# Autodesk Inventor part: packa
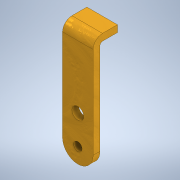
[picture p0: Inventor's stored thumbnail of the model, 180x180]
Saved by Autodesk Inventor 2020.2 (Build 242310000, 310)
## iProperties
Created: 2020-04
Part Number: packa
Material: Brass, Soft Yellow, Welded
Document SubType Name: Modeling
Designer: freem
Density: 8.5 g/cm^3
Appearance: Weld - Brass
Author: freem
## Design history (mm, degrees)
sketch "Sketch1"
  geometry: L1 (0, 4)-(63, 4); L2 (68.5, -1.5)-(68.5, -10.3); L3 (63, -1.5)-(96.882, 32.382); L4 (64.5, -10.3)-(64.5, -1.5); L5 (63, 0)-(0, 0); L6 (68.5, -10.3)-(64.5, -10.3); L7 (0, 0)-(0, 4); A1 r 5.5 centre (63, -1.5) between (68.5, -1.5) and (63, 4); A2 r 1.5 centre (63, -1.5) between (64.5, -1.5) and (63, 0); 1 further point
  constraints: 14 end point, 4 point on circle, 2 centre point, 2 horizontal, 2 tangent, 1 coincident, 1 perpendicular, 1 symmetric about line, 1 vertical, 2 other
  dimensions: "d2" = 5.5 radius of A1; "d3" = 4 distance between parallel lines of L2 L4; "d4" = 68.5 distance between parallel lines of L2 L7; "d5" = 14.3 distance between parallel lines of L1 L6
extrude "Extrusion1" new body sketch "Sketch1" distance "d6" = 18; taper "d7" = 0 deg
fillet "Fillet1" dims "d8" = 9
sketch "Sketch2"
  geometry: A1 r 9 centre (9, -54) between (0, -54) and (18, -54) reference; 3 further points
  constraints: 1 coincident
  dimensions: "d9" = 17 distance of point (9, -37) point (9, -54)
hole "Hole1" sketch "Sketch2" diameter "d10" = 5; stored, may be unused: countersink angle "d14" = 80 deg, drill point angle "d16" = 120 deg; dims "d11" = 10, "d12" = 5, "d13" = 2, "d15" = 12
hole "Hole2" sketch "Sketch2" diameter "d17" = 7; stored, may be unused: countersink angle "d21" = 80 deg, drill point angle "d23" = 120 deg; dims "d18" = 10, "d19" = 5, "d20" = 2, "d22" = 12
body "Solid1"
